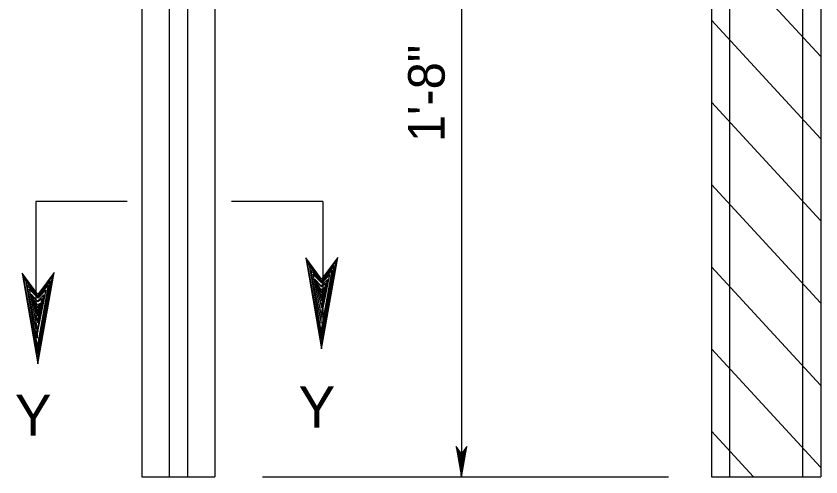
# Model space of a CAD drawing. Extents: x 499883 to 500983, y 499104 to 499764.
# Drawn here: x 500576.3 to 500664.4, y 499170.7 to 499221.1 of the extents above; entities that cross this region are included whole.
import ezdxf

# ---------------------------------------------------------------- set-up
doc = ezdxf.new("R2010")
doc.units = 0
for name, color, linetype in [('1', 7, 'Continuous'), ('2', 7, 'Continuous'), ('5', 7, 'Continuous'), ('60', 7, 'Continuous')]:
    doc.layers.add(name, color=color, linetype=linetype)

msp = doc.modelspace()

# ---------------------------------------------------------------- linework, layer by layer
at = {"layer": '1'}
for p, q in [((500652.382, 499229.611), (500664.324, 499216.671)), ((500652.382, 499220.618), (500664.324, 499207.678)), ((500652.382, 499211.625), (500664.324, 499198.685)), ((500652.382, 499202.632), (500664.324, 499189.691)), ((500652.382, 499193.639), (500664.324, 499180.698)), ((500652.382, 499184.646), (500664.324, 499171.705)), ((500652.382, 499175.652), (500656.993, 499170.656))]:
    msp.add_line(p, q, dxfattribs=at)
at = {"layer": '2'}
for p, q in [((500593.056, 499265.584), (500593.056, 499170.656)), ((500595.054, 499265.584), (500595.054, 499170.656)), ((500590.058, 499247.084), (500590.058, 499170.656)), ((500598.052, 499247.044), (500598.052, 499170.656)), ((500578.467, 499200.784), (500578.467, 499185.863)), ((500609.861, 499200.784), (500609.861, 499185.863))]:
    msp.add_line(p, q, dxfattribs=at)
at = {"layer": '5'}
for p, q in [((500652.382, 499265.584), (500652.382, 499170.656)), ((500654.381, 499265.584), (500654.381, 499170.656)), ((500662.374, 499265.499), (500662.374, 499170.656)), ((500664.373, 499265.499), (500664.373, 499170.656)), ((500625.024, 499245.588), (500625.024, 499170.656)), ((500588.459, 499200.784), (500578.467, 499200.784)), ((500609.861, 499200.784), (500599.868, 499200.784)), ((500590.058, 499170.656), (500598.052, 499170.656)), ((500603.246, 499170.656), (500647.706, 499170.656))]:
    msp.add_line(p, q, dxfattribs=at)
for points in [[(500609.727, 499184.679), (500611.49, 499194.65), (500609.727, 499192.268), (500607.992, 499194.599), (500609.727, 499184.679), (500609.708, 499185.341), (500611.359, 499194.371), (500609.705, 499192.082), (500608.129, 499194.196), (500609.678, 499185.698), (500609.727, 499186.03), (500611.101, 499193.766), (500609.706, 499192.03), (500608.353, 499193.815), (500609.727, 499186.182), (500609.678, 499186.513), (500610.898, 499193.275), (500609.727, 499191.96), (500608.511, 499193.303), (500609.677, 499187.477), (500609.677, 499188.039), (500610.646, 499192.773), (500609.755, 499191.853), (500608.763, 499192.844), (500609.727, 499188.139), (500609.757, 499188.672), (500610.367, 499192.232), (500609.676, 499191.547), (500608.994, 499192.289), (500609.727, 499189.161), (500609.777, 499189.664), (500610.186, 499191.801), (500609.705, 499191.449), (500609.173, 499192.032), (500609.728, 499189.924), (500610.058, 499191.318), (500609.677, 499191.117), (500609.295, 499191.729), (500609.676, 499190.274), (500609.905, 499191.189), (500609.604, 499190.807), (500609.424, 499191.246), (500609.705, 499190.809), (500609.755, 499191.038)], [(500578.68, 499183.021), (500580.443, 499192.992), (500578.68, 499190.61), (500576.945, 499192.941), (500578.68, 499183.021), (500578.661, 499183.683), (500580.312, 499192.713), (500578.659, 499190.424), (500577.082, 499192.538), (500578.631, 499184.04), (500578.68, 499184.373), (500580.055, 499192.108), (500578.66, 499190.372), (500577.306, 499192.157), (500578.681, 499184.524), (500578.631, 499184.855), (500579.851, 499191.618), (500578.681, 499190.302), (500577.464, 499191.645), (500578.63, 499185.819), (500578.63, 499186.381), (500579.6, 499191.116), (500578.708, 499190.195), (500577.716, 499191.187), (500578.68, 499186.481), (500578.71, 499187.014), (500579.32, 499190.574), (500578.629, 499189.89), (500577.947, 499190.631), (500578.68, 499187.503), (500578.73, 499188.006), (500579.139, 499190.143), (500578.659, 499189.792), (500578.126, 499190.374), (500578.682, 499188.266), (500579.012, 499189.66), (500578.63, 499189.459), (500578.248, 499190.071), (500578.629, 499188.617), (500578.859, 499189.532), (500578.557, 499189.148), (500578.377, 499189.588), (500578.659, 499189.15), (500578.708, 499189.38)], [(500625.024, 499170.656), (500625.611, 499173.98), (500625.024, 499173.186), (500624.446, 499173.963), (500625.024, 499170.656), (500625.017, 499170.877), (500625.568, 499173.887), (500625.017, 499173.124), (500624.491, 499173.829), (500625.007, 499170.996), (500625.024, 499171.107), (500625.482, 499173.685), (500625.017, 499173.106), (500624.566, 499173.702), (500625.024, 499171.157), (500625.007, 499171.268), (500625.414, 499173.522), (500625.024, 499173.083), (500624.619, 499173.531), (500625.007, 499171.589), (500625.007, 499171.776), (500625.33, 499173.354), (500625.033, 499173.047), (500624.703, 499173.378), (500625.024, 499171.81), (500625.034, 499171.987), (500625.237, 499173.174), (500625.007, 499172.946), (500624.779, 499173.193), (500625.024, 499172.15), (500625.041, 499172.318), (500625.177, 499173.03), (500625.017, 499172.913), (500624.839, 499173.107), (500625.024, 499172.404), (500625.135, 499172.869), (500625.007, 499172.802), (500624.88, 499173.006), (500625.007, 499172.521), (500625.083, 499172.827), (500624.983, 499172.699), (500624.923, 499172.845), (500625.017, 499172.699), (500625.033, 499172.776)]]:
    msp.add_lwpolyline(points, dxfattribs=at)
at = {"layer": '60'}
msp.add_line((500652.382, 499170.656), (500664.373, 499170.656), dxfattribs=at)

# ---------------------------------------------------------------- texts
at = {"layer": '5'}
msp.add_text('1\'-8"', height=4, rotation=90, dxfattribs=at).set_placement((500623.198, 499207.262))
for p in [(500607.208, 499176.057), (500576.162, 499175.152)]:
    msp.add_text('Y', height=4.5, dxfattribs=at).set_placement(p)

doc.saveas('drawing.dxf')
